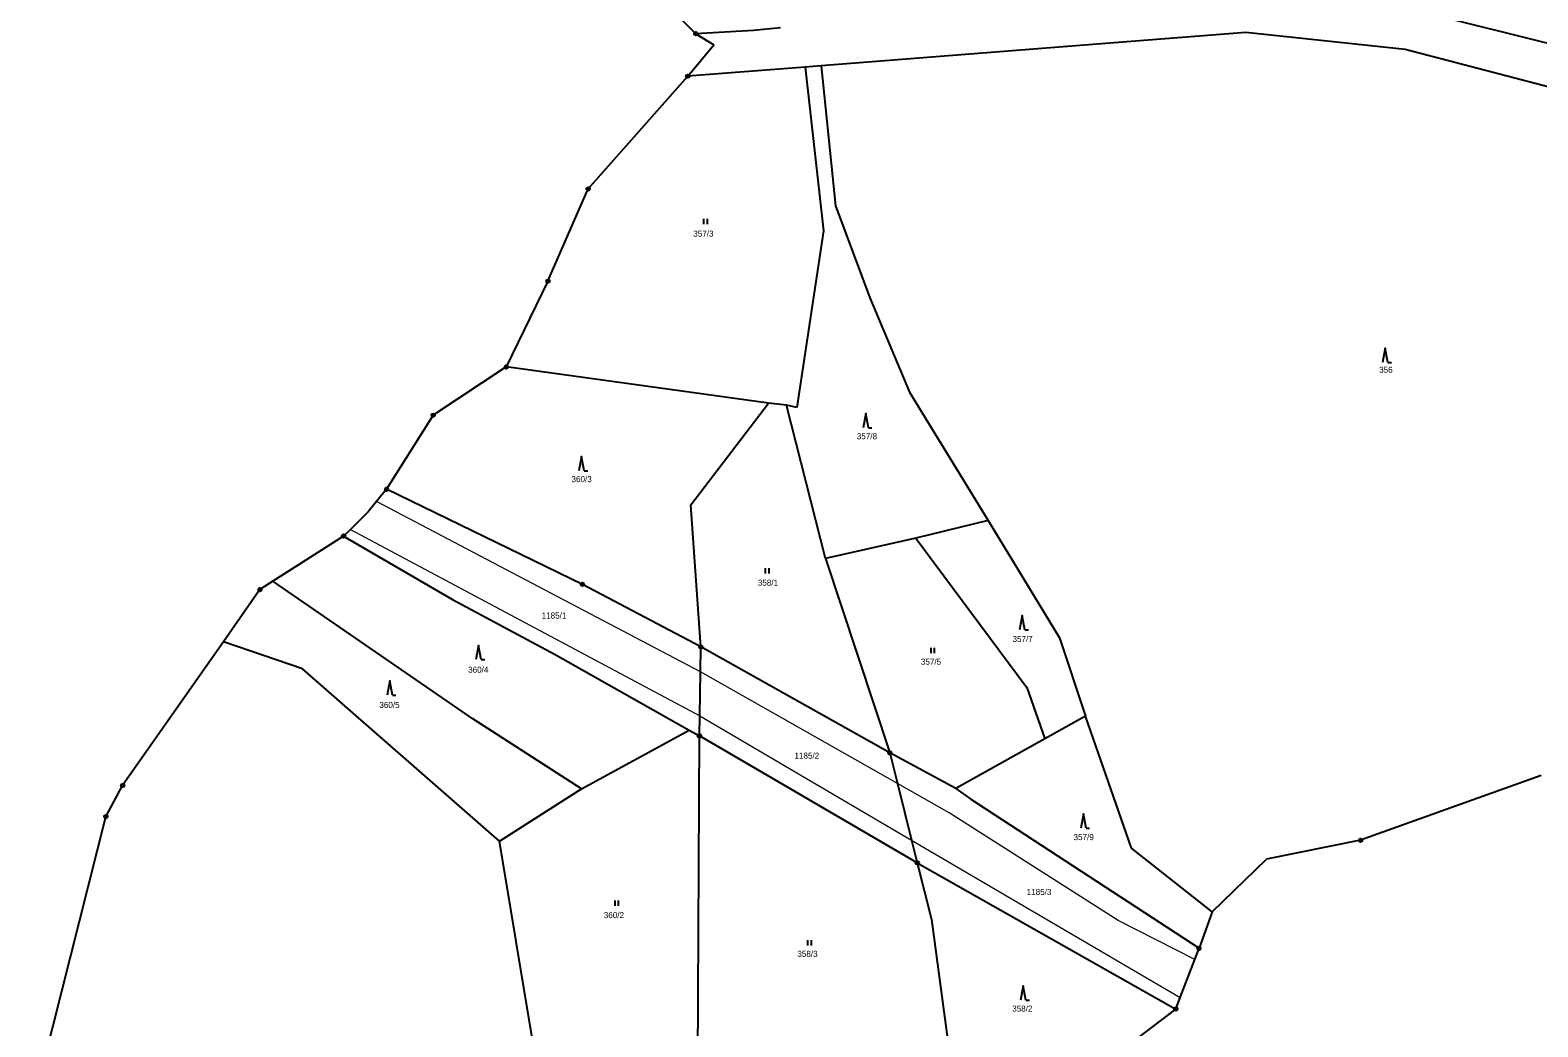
# Model space of a CAD drawing. Extents: x -765428 to -762163, y -1107632 to -1104975.
# Drawn here: x -764480.8 to -764056.9, y -1107441.1 to -1107160.9 of the extents above; entities that cross this region are included whole.
import ezdxf

# ---------------------------------------------------------------- set-up
doc = ezdxf.new("R2010")
doc.units = 0
doc.header["$LTSCALE"] = 0.68
for name, color, linetype, lineweight in [('1', 7, 'Continuous', 25), ('3', 7, 'Continuous', 25), ('4', 7, 'Continuous', 13), ('8', 7, 'Continuous', 25)]:
    doc.layers.add(name, color=color, linetype=linetype, lineweight=lineweight)
doc.layers.add('2', color=7, linetype='Continuous')

msp = doc.modelspace()

# ---------------------------------------------------------------- linework, layer by layer
at = {"layer": '1'}
for p, q in [((-764302.2, -1107153.46), (-764293.68, -1107161.91)), ((-764092.57, -1107154.99), (-764025.72, -1107171.67)), ((-764277.42, -1107161.04), (-764293.68, -1107161.91)), ((-764293.68, -1107161.91), (-764288.66, -1107165.04)), ((-764269.84, -1107160.28), (-764277.42, -1107161.04)), ((-764139.08, -1107161.59), (-764258.46, -1107170.93)), ((-764094.29, -1107166.37), (-764139.08, -1107161.59)), ((-764007.56, -1107188.99), (-764094.29, -1107166.37)), ((-764262.9, -1107171.27), (-764295.95, -1107173.86)), ((-764258.46, -1107170.93), (-764262.9, -1107171.27)), ((-764262.9, -1107171.27), (-764257.74, -1107217.37)), ((-764258.46, -1107170.93), (-764254.39, -1107210.26)), ((-764335.24, -1107231.49), (-764323.96, -1107205.56)), ((-764254.39, -1107210.26), (-764244.77, -1107236.18)), ((-764257.74, -1107217.37), (-764265.32, -1107266.99)), ((-764335.24, -1107231.49), (-764346.96, -1107255.6)), ((-764244.77, -1107236.18), (-764233.59, -1107262.65)), ((-764346.96, -1107255.6), (-764367.51, -1107269.16)), ((-764273.24, -1107265.8), (-764346.96, -1107255.6)), ((-764233.59, -1107262.65), (-764211.46, -1107298.73)), ((-764295.07, -1107294.39), (-764273.24, -1107265.8)), ((-764268.19, -1107266.36), (-764273.24, -1107265.8)), ((-764265.32, -1107266.99), (-764268.19, -1107266.36)), ((-764257.2, -1107309.45), (-764268.19, -1107266.36)), ((-764367.51, -1107269.16), (-764380.61, -1107290)), ((-764383.46, -1107293.47), (-764385.82, -1107296.36)), ((-764380.61, -1107290), (-764383.46, -1107293.47)), ((-764325.55, -1107316.73), (-764380.61, -1107290)), ((-764385.82, -1107296.36), (-764390.79, -1107301.25)), ((-764292.25, -1107334.32), (-764295.07, -1107294.39)), ((-764390.79, -1107301.25), (-764392.71, -1107303.15)), ((-764211.46, -1107298.73), (-764231.79, -1107303.7)), ((-764211.46, -1107298.73), (-764191.41, -1107331.77)), ((-764392.71, -1107303.15), (-764412.57, -1107315.86)), ((-764392.71, -1107303.15), (-764362.06, -1107321)), ((-764231.79, -1107303.7), (-764257.2, -1107309.45)), ((-764231.79, -1107303.7), (-764200.63, -1107345.68)), ((-764257.2, -1107309.45), (-764239.13, -1107364.1)), ((-764416.22, -1107318.19), (-764426.5, -1107332.86)), ((-764412.57, -1107315.86), (-764416.22, -1107318.19)), ((-764356.34, -1107354.5), (-764412.57, -1107315.86)), ((-764292.25, -1107334.32), (-764325.55, -1107316.73)), ((-764362.06, -1107321), (-764333.24, -1107336.41)), ((-764426.5, -1107332.86), (-764454.83, -1107373.27)), ((-764404.3, -1107340.44), (-764426.5, -1107332.86)), ((-764292.37, -1107341.31), (-764292.25, -1107334.32)), ((-764239.13, -1107364.1), (-764292.25, -1107334.32)), ((-764191.41, -1107331.77), (-764184.11, -1107353.73)), ((-764333.24, -1107336.41), (-764295.51, -1107357.71)), ((-764348.86, -1107388.89), (-764404.3, -1107340.44)), ((-764292.58, -1107353.69), (-764292.37, -1107341.31)), ((-764200.63, -1107345.68), (-764195.6, -1107360.14)), ((-764325.81, -1107374.25), (-764356.34, -1107354.5)), ((-764292.67, -1107359.32), (-764292.58, -1107353.69)), ((-764184.11, -1107353.73), (-764195.6, -1107360.14)), ((-764171.17, -1107390.93), (-764184.11, -1107353.73)), ((-764325.81, -1107374.25), (-764295.51, -1107357.71)), ((-764295.51, -1107357.71), (-764292.67, -1107359.32)), ((-764293.26, -1107473.11), (-764292.67, -1107359.32)), ((-764231.43, -1107395.01), (-764292.67, -1107359.32)), ((-764195.6, -1107360.14), (-764220.59, -1107374.08)), ((-764220.59, -1107374.08), (-764239.13, -1107364.1)), ((-764239.13, -1107364.1), (-764236.98, -1107372.71)), ((-764459.56, -1107382.03), (-764454.83, -1107373.27)), ((-764236.98, -1107372.71), (-764233.03, -1107388.59)), ((-764220.59, -1107374.08), (-764216.33, -1107377.12)), ((-764056.01, -1107370.44), (-764106.78, -1107388.67)), ((-764348.86, -1107388.89), (-764325.81, -1107374.25)), ((-764216.33, -1107377.12), (-764152.2, -1107419.03)), ((-764480.83, -1107466.41), (-764459.56, -1107382.03)), ((-764339.49, -1107445.38), (-764348.86, -1107388.89)), ((-764233.03, -1107388.59), (-764231.43, -1107395.01)), ((-764148.54, -1107408.79), (-764171.17, -1107390.93)), ((-764106.78, -1107388.67), (-764133.27, -1107394.02)), ((-764231.43, -1107395.01), (-764227.42, -1107410.92)), ((-764231.43, -1107395.01), (-764158.7, -1107436.11)), ((-764148.54, -1107408.79), (-764133.27, -1107394.02)), ((-764227.42, -1107410.92), (-764219.48, -1107470.01)), ((-764148.54, -1107408.79), (-764152.2, -1107419.03)), ((-764153.4, -1107422.17), (-764152.2, -1107419.03)), ((-764157.49, -1107432.91), (-764153.4, -1107422.17)), ((-764158.7, -1107436.11), (-764157.49, -1107432.91)), ((-764194.79, -1107463.46), (-764158.7, -1107436.11))]:
    msp.add_line(p, q, dxfattribs=at)
msp.add_lwpolyline([(-764323.96, -1107205.56), (-764295.95, -1107173.86), (-764288.66, -1107165.04)], dxfattribs=at)
at = {"layer": '3'}
for p, q in [((-764291.421, -1107215.48), (-764291.421, -1107213.98)), ((-764290.42, -1107215.48), (-764290.42, -1107213.98)), ((-764099.12, -1107254.31), (-764098.124, -1107254.31)), ((-764245.16, -1107272.69), (-764244.164, -1107272.69)), ((-764325.06, -1107284.78), (-764324.064, -1107284.78)), ((-764274.071, -1107313.63), (-764274.071, -1107312.13)), ((-764273.07, -1107313.63), (-764273.07, -1107312.13)), ((-764201.18, -1107329.51), (-764200.184, -1107329.51)), ((-764227.551, -1107336.06), (-764227.551, -1107334.56)), ((-764226.55, -1107336.06), (-764226.55, -1107334.56)), ((-764354.01, -1107337.89), (-764353.014, -1107337.89)), ((-764379, -1107347.85), (-764378.004, -1107347.85)), ((-764183.98, -1107385.22), (-764182.984, -1107385.22)), ((-764316.381, -1107407.1), (-764316.381, -1107405.6)), ((-764315.38, -1107407.1), (-764315.38, -1107405.6)), ((-764262.141, -1107418.23), (-764262.141, -1107416.73)), ((-764261.14, -1107418.23), (-764261.14, -1107416.73)), ((-764200.88, -1107433.6), (-764199.884, -1107433.6))]:
    msp.add_line(p, q, dxfattribs=at)
for points in [[(-764099.12, -1107254.31), (-764099.87, -1107250.31), (-764100.62, -1107254.31)], [(-764245.16, -1107272.69), (-764245.91, -1107268.69), (-764246.66, -1107272.69)], [(-764325.06, -1107284.78), (-764325.81, -1107280.78), (-764326.56, -1107284.78)], [(-764201.18, -1107329.51), (-764201.93, -1107325.51), (-764202.68, -1107329.51)], [(-764354.01, -1107337.89), (-764354.76, -1107333.89), (-764355.51, -1107337.89)], [(-764379, -1107347.85), (-764379.75, -1107343.85), (-764380.5, -1107347.85)], [(-764183.98, -1107385.22), (-764184.73, -1107381.22), (-764185.48, -1107385.22)], [(-764200.88, -1107433.6), (-764201.63, -1107429.6), (-764202.38, -1107433.6)]]:
    msp.add_lwpolyline(points, dxfattribs=at)
at = {"layer": '4'}
for p, q in [((-764292.37, -1107341.31), (-764383.46, -1107293.47)), ((-764390.79, -1107301.25), (-764292.58, -1107353.69)), ((-764236.98, -1107372.71), (-764292.37, -1107341.31)), ((-764292.58, -1107353.69), (-764233.03, -1107388.59)), ((-764222.43, -1107380.95), (-764236.98, -1107372.71)), ((-764174.92, -1107411.22), (-764222.43, -1107380.95)), ((-764233.03, -1107388.59), (-764157.49, -1107432.91)), ((-764153.4, -1107422.17), (-764174.92, -1107411.22))]:
    msp.add_line(p, q, dxfattribs=at)
at = {"layer": '8'}
for centre, radius in [((-764293.68, -1107161.9099), 0.5), ((-764293.68, -1107161.9099), 0.0303), ((-764295.95, -1107173.8599), 0.5), ((-764295.95, -1107173.8599), 0.0303), ((-764323.96, -1107205.5599), 0.5), ((-764323.96, -1107205.5599), 0.0303), ((-764335.24, -1107231.4899), 0.5), ((-764335.24, -1107231.4899), 0.0303), ((-764346.96, -1107255.5999), 0.5), ((-764346.96, -1107255.5999), 0.0303), ((-764367.51, -1107269.1599), 0.5), ((-764367.51, -1107269.1599), 0.0303), ((-764380.61, -1107289.9999), 0.5), ((-764380.61, -1107289.9999), 0.0303), ((-764392.71, -1107303.1499), 0.5), ((-764392.71, -1107303.1499), 0.0303), ((-764416.22, -1107318.1899), 0.5), ((-764416.22, -1107318.1899), 0.0303), ((-764325.55, -1107316.7299), 0.5), ((-764325.55, -1107316.7299), 0.0303), ((-764292.25, -1107334.3199), 0.5), ((-764292.25, -1107334.3199), 0.0303), ((-764292.67, -1107359.3199), 0.5), ((-764292.67, -1107359.3199), 0.0303), ((-764239.13, -1107364.0999), 0.5), ((-764239.13, -1107364.0999), 0.0303), ((-764454.83, -1107373.2699), 0.5), ((-764454.83, -1107373.2699), 0.0303), ((-764459.56, -1107382.0299), 0.5), ((-764459.56, -1107382.0299), 0.0303), ((-764106.78, -1107388.6699), 0.5), ((-764106.78, -1107388.6699), 0.0303), ((-764231.43, -1107395.0099), 0.5), ((-764231.43, -1107395.0099), 0.0303), ((-764152.2, -1107419.0299), 0.5), ((-764152.2, -1107419.0299), 0.0303), ((-764158.7, -1107436.1099), 0.5), ((-764158.7, -1107436.1099), 0.0303)]:
    msp.add_circle(centre, radius, dxfattribs=at)

# ---------------------------------------------------------------- texts
at = {"layer": '2'}
for s, p in [('357/3', (-764294.39, -1107218.975)), ('356', (-764101.56, -1107257.235)), ('357/8', (-764248.42, -1107275.925)), ('360/3', (-764328.63, -1107287.985)), ('358/1', (-764276.24, -1107317.085)), ('1185/1', (-764337.02, -1107326.325)), ('357/7', (-764204.63, -1107332.925)), ('360/4', (-764357.68, -1107341.555)), ('357/5', (-764230.4, -1107339.295)), ('360/5', (-764382.64, -1107351.465)), ('1185/2', (-764265.95, -1107365.735)), ('357/9', (-764187.49, -1107388.625)), ('1185/3', (-764200.65, -1107404.045)), ('360/2', (-764319.55, -1107410.555)), ('358/3', (-764265.12, -1107421.445)), ('358/2', (-764204.72, -1107436.835))]:
    msp.add_text(s, height=1.7, dxfattribs=at).set_placement(p)

doc.saveas('drawing.dxf')
